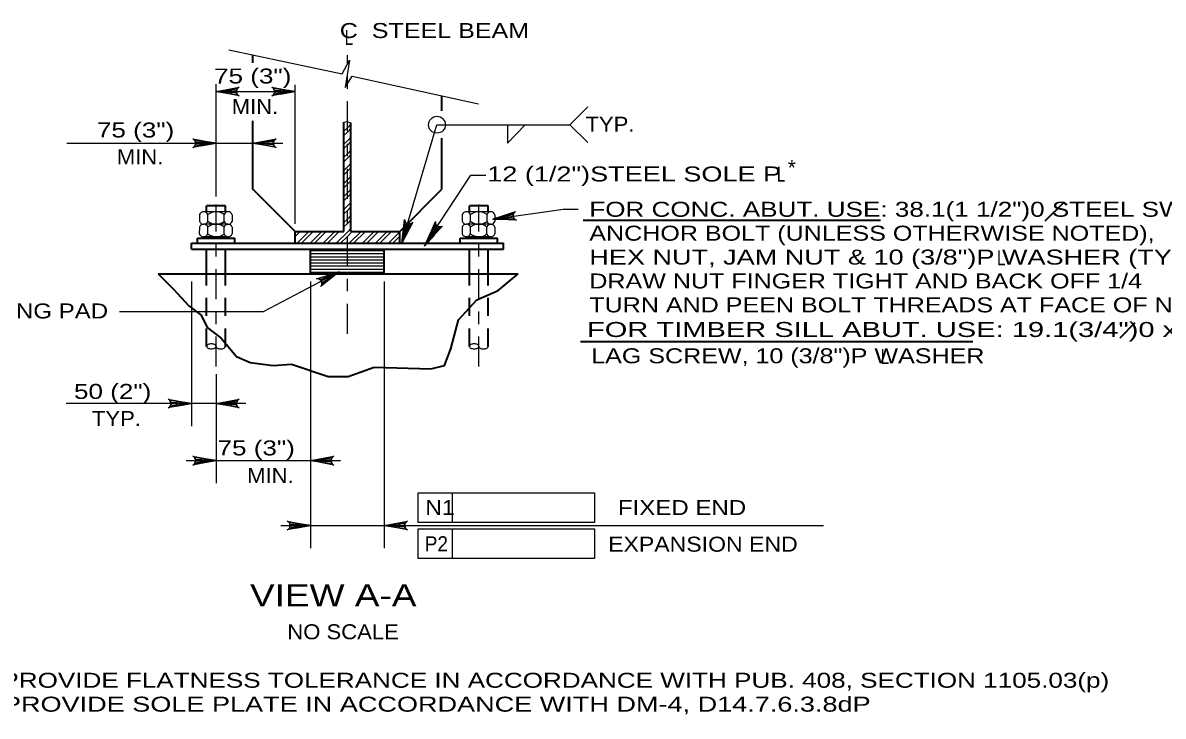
# Model space of a CAD drawing. Extents: x -11 to 79, y -154 to 0.
# Drawn here: x 14 to 23.13, y -147.7 to -142.15 of the extents above; entities that cross this region are included whole.
import ezdxf
from ezdxf.enums import TextEntityAlignment as Align

# ---------------------------------------------------------------- set-up
doc = ezdxf.new("R2010")
doc.units = 0
doc.header["$LTSCALE"] = 0.048
doc.linetypes.add('DOT_DASHED', pattern=[7.7, 5, -1.2, 0.3, -1.2])
doc.linetypes.add('MEDIUM_DASHED', pattern=[4.5, 3, -1.5])
for name, color, linetype, lineweight in [('3', 7, 'Continuous', 25), ('4', 7, 'Continuous', 25), ('8', 7, 'Continuous', 35)]:
    doc.layers.add(name, color=color, linetype=linetype, lineweight=lineweight)

msp = doc.modelspace()

# ---------------------------------------------------------------- hatches: boundary and pattern name
at = {"layer": '4'}
for points in [[(15.6685, -142.68467), (15.6685, -142.72458), (15.5485, -142.70458)], [(16.0615, -142.68467), (16.0615, -142.72458), (16.1815, -142.70458)], [(15.4285, -143.09783), (15.4285, -143.13783), (15.5485, -143.11783)], [(15.96383, -143.09783), (15.96383, -143.13783), (15.84383, -143.11783)], [(17.887, -143.72833), (17.8815, -143.68875), (17.76542, -143.72525)], [(17.09008, -143.80825), (17.052, -143.79592), (17.03408, -143.91625)], [(17.26717, -143.82925), (17.30067, -143.85108), (17.21833, -143.94067)], [(15.23167, -145.18158), (15.23167, -145.22158), (15.35167, -145.20158)], [(15.6685, -145.18158), (15.6685, -145.22158), (15.5485, -145.20158)], [(15.4285, -145.63775), (15.4285, -145.67775), (15.5485, -145.65775)], [(16.425, -145.63775), (16.425, -145.67775), (16.305, -145.65775)], [(16.185, -146.15725), (16.185, -146.19725), (16.305, -146.17725)], [(17.0155, -146.15725), (17.0155, -146.19725), (16.8955, -146.17725)]]:
    msp.add_hatch(color=256, dxfattribs=at).paths.add_polyline_path(points)

# ---------------------------------------------------------------- linework, layer by layer
at = {"layer": '3', "lineweight": 35}
for p, q in [((15.84383, -142.47458), (15.84383, -142.41092)), ((17.35675, -142.85967), (17.35675, -142.73908)), ((15.84383, -143.48667), (15.84383, -142.93842)), ((16.57217, -143.82442), (16.57217, -142.95008)), ((16.62842, -143.82442), (16.62842, -142.955)), ((17.35675, -143.48667), (17.35675, -143.0785)), ((15.6235, -143.61992), (15.4735, -143.61958)), ((15.4735, -143.66592), (15.4735, -143.61958)), ((15.6235, -143.66625), (15.6235, -143.61992)), ((17.577, -143.66592), (17.577, -143.61958)), ((17.727, -143.61992), (17.577, -143.61958)), ((17.727, -143.66625), (17.727, -143.61992)), ((16.1815, -143.91808), (16.1815, -143.82442)), ((16.1815, -143.82442), (16.57217, -143.82442)), ((16.62842, -143.82442), (17.019, -143.82442)), ((17.019, -143.91808), (17.019, -143.82442)), ((17.577, -143.87875), (17.577, -143.86592)), ((17.727, -143.87875), (17.727, -143.86625)), ((15.35167, -143.91808), (17.84883, -143.91808)), ((15.35167, -143.96533), (15.35167, -143.91808)), ((15.39892, -143.87875), (15.69817, -143.87875)), ((15.39892, -143.91808), (15.39892, -143.87875)), ((15.69817, -143.91808), (15.69817, -143.87875)), ((17.50242, -143.87875), (17.80158, -143.87875)), ((17.50242, -143.91808), (17.50242, -143.87875)), ((17.80158, -143.91808), (17.80158, -143.87875)), ((17.84883, -143.96533), (17.84883, -143.91808)), ((15.35167, -143.96533), (17.84883, -143.96533)), ((15.4735, -144.16225), (15.4735, -143.96533)), ((15.6235, -144.16225), (15.6235, -143.96533)), ((16.305, -144.16225), (16.305, -143.96533)), ((16.8955, -144.16225), (16.8955, -143.96533)), ((17.577, -144.16225), (17.577, -143.96533)), ((17.727, -144.16225), (17.727, -143.96533)), ((15.08642, -144.16225), (17.967, -144.16225))]:
    msp.add_line(p, q, dxfattribs=at)
at = {"layer": '3', "linetype": 'DOT_DASHED'}
for p, q in [((16.60025, -144.64183), (16.60025, -142.41183)), ((15.5485, -144.90458), (15.5485, -143.60717)), ((17.652, -144.90458), (17.652, -143.60717))]:
    msp.add_line(p, q, dxfattribs=at)
at = {"layer": '3'}
for p, q in [((16.57217, -142.95225), (16.57475, -142.94958)), ((16.57217, -143.43942), (16.60025, -143.41125)), ((16.60025, -143.41125), (16.62842, -143.38317)), ((16.57217, -143.47417), (16.60025, -143.44608)), ((16.60025, -143.44608), (16.62842, -143.41792)), ((16.60025, -143.51567), (16.62842, -143.48758)), ((16.57217, -143.54383), (16.60025, -143.51567)), ((16.57217, -143.57858), (16.60025, -143.5505)), ((16.60025, -143.5505), (16.62842, -143.52233)), ((16.60025, -143.62008), (16.62842, -143.59192)), ((15.64717, -143.66625), (15.448, -143.66583)), ((16.57217, -143.64817), (16.60025, -143.62008)), ((16.57217, -143.683), (16.60025, -143.65483)), ((16.60025, -143.65483), (16.62842, -143.62675)), ((17.75067, -143.66625), (17.5515, -143.66583)), ((15.41508, -143.689), (15.415, -143.74258)), ((15.647, -143.76625), (15.44775, -143.76583)), ((15.48292, -143.74275), (15.48308, -143.68908)), ((15.61417, -143.743), (15.61433, -143.68942)), ((15.67758, -143.6895), (15.6775, -143.74317)), ((16.57217, -143.75258), (16.60025, -143.7245)), ((16.57217, -143.78742), (16.60025, -143.75925)), ((16.60025, -143.7245), (16.62842, -143.69633)), ((16.60025, -143.75925), (16.62842, -143.73117)), ((17.51858, -143.689), (17.5185, -143.74258)), ((17.75042, -143.76625), (17.55125, -143.76583)), ((17.58642, -143.74275), (17.58658, -143.68908)), ((17.71767, -143.743), (17.71783, -143.68942)), ((17.78108, -143.6895), (17.781, -143.74317)), ((15.41492, -143.789), (15.41483, -143.84258)), ((15.64675, -143.86625), (15.44758, -143.86583)), ((15.4735, -143.87875), (15.4735, -143.86592)), ((15.48275, -143.84275), (15.48283, -143.78917)), ((15.614, -143.843), (15.61408, -143.78942)), ((15.6235, -143.87875), (15.6235, -143.86625)), ((15.67742, -143.78958), (15.67733, -143.84317)), ((16.1815, -143.83), (16.18717, -143.82442)), ((16.1815, -143.86483), (16.222, -143.82442)), ((16.19783, -143.91808), (16.29158, -143.82442)), ((16.23258, -143.91808), (16.32633, -143.82442)), ((16.30225, -143.91808), (16.39592, -143.82442)), ((16.337, -143.91808), (16.43075, -143.82442)), ((16.40658, -143.91808), (16.50033, -143.82442)), ((16.44142, -143.91808), (16.53517, -143.82442)), ((16.61542, -143.91808), (16.70917, -143.82442)), ((16.65017, -143.91808), (16.74392, -143.82442)), ((16.71983, -143.91808), (16.8135, -143.82442)), ((16.75458, -143.91808), (16.84833, -143.82442)), ((16.82417, -143.91808), (16.91792, -143.82442)), ((16.859, -143.91808), (16.95275, -143.82442)), ((16.92858, -143.91808), (17.019, -143.82775)), ((16.96342, -143.91808), (17.019, -143.8625)), ((17.51842, -143.789), (17.51825, -143.84258)), ((17.75025, -143.86625), (17.55108, -143.86583)), ((17.58625, -143.84275), (17.58633, -143.78917)), ((17.7175, -143.843), (17.71758, -143.78942)), ((17.78092, -143.78958), (17.78075, -143.84317)), ((16.305, -143.96542), (16.30492, -143.96533)), ((15.62483, -144.16225), (15.6235, -144.16092)), ((17.5695, -144.16225), (17.577, -144.15467))]:
    msp.add_line(p, q, dxfattribs=at)
at = {"layer": '3', "linetype": 'MEDIUM_DASHED', "lineweight": 35}
for p, q in [((15.4735, -144.74417), (15.4735, -144.16225)), ((15.6235, -144.74417), (15.6235, -144.16225)), ((17.577, -144.74417), (17.577, -144.16225)), ((17.727, -144.74417), (17.727, -144.16225))]:
    msp.add_line(p, q, dxfattribs=at)
at = {"layer": '3'}
for points in [[(16.57217, -142.95008), (16.598, -142.94525), (16.62842, -142.955)], [(16.57217, -143.02183), (16.60025, -142.99367), (16.62842, -142.96558)], [(16.57217, -143.05658), (16.60025, -143.0285), (16.62842, -143.00042)], [(16.57217, -143.12625), (16.60025, -143.09808), (16.62842, -143.07)], [(16.57217, -143.161), (16.60025, -143.13292), (16.62842, -143.10475)], [(16.57217, -143.23058), (16.60025, -143.2025), (16.62842, -143.17433)], [(16.57217, -143.26542), (16.60025, -143.23725), (16.62842, -143.20917)], [(16.57217, -143.335), (16.60025, -143.30692), (16.62842, -143.27875)], [(16.57217, -143.36983), (16.60025, -143.34167), (16.62842, -143.31358)], [(16.511, -143.91808), (16.60025, -143.82883), (16.62842, -143.80075)], [(16.54583, -143.91808), (16.60025, -143.86367), (16.63958, -143.82442)], [(16.305, -143.97667), (16.60025, -143.97667), (16.8955, -143.97667)], [(16.305, -144.00133), (16.60025, -144.00133), (16.8955, -144.00133)], [(16.305, -144.02592), (16.60025, -144.02592), (16.8955, -144.02592)], [(16.305, -144.0505), (16.60025, -144.0505), (16.8955, -144.0505)], [(16.305, -144.07517), (16.60025, -144.07517), (16.8955, -144.07517)], [(16.305, -144.09975), (16.60025, -144.09975), (16.8955, -144.09975)], [(16.305, -144.12433), (16.60025, -144.12433), (16.8955, -144.12433)], [(16.305, -144.14892), (16.60025, -144.14892), (16.8955, -144.14892)]]:
    msp.add_lwpolyline(points, dxfattribs=at)
at = {"layer": '3', "lineweight": 35}
msp.add_lwpolyline([(15.08642, -144.16225), (15.209, -144.28475), (15.33158, -144.4195), (15.42967, -144.49308), (15.47867, -144.59108), (15.589, -144.67683), (15.71158, -144.82383), (15.82192, -144.87292), (16.00575, -144.89742), (16.15283, -144.88517), (16.44708, -144.98317), (16.60642, -144.98317), (16.81475, -144.90967), (17.26833, -144.92192), (17.37867, -144.89742), (17.42767, -144.76258), (17.48892, -144.52983), (17.636, -144.3705), (17.80767, -144.297), (17.967, -144.16225)], dxfattribs=at)
at = {"layer": '3'}
for centre, radius, start, end in [((15.44903, -143.70227), 0.03646, 88.05447, 158.59459), ((15.44903, -143.70227), 0.03646, 21.16848, 88.05447), ((15.54849, -143.77042), 0.10439, 50.93154, 128.83154), ((15.64591, -143.69939), 0.03318, 17.33335, 162.42973), ((17.55252, -143.70227), 0.03646, 88.05447, 158.59459), ((17.55252, -143.70227), 0.03646, 21.16848, 88.05447), ((17.65198, -143.77042), 0.10439, 50.93154, 128.83154), ((17.7494, -143.69939), 0.03318, 17.33335, 162.42973), ((15.44883, -143.80228), 0.03646, 88.05447, 158.59459), ((15.44898, -143.7294), 0.03646, 201.16848, 271.7086), ((15.44898, -143.7294), 0.03646, 271.7086, 338.59459), ((15.44883, -143.80228), 0.03646, 21.16848, 88.05447), ((15.54829, -143.87044), 0.10439, 50.93154, 128.83154), ((15.54872, -143.66166), 0.10439, 230.93154, 308.83154), ((15.64571, -143.7994), 0.03318, 17.33335, 162.42973), ((15.64584, -143.73309), 0.03318, 197.33335, 342.42973), ((17.55231, -143.80228), 0.03646, 88.05447, 158.59459), ((17.55246, -143.7294), 0.03646, 201.16848, 271.7086), ((17.55246, -143.7294), 0.03646, 271.7086, 338.59459), ((17.55231, -143.80228), 0.03646, 21.16848, 88.05447), ((17.65177, -143.87044), 0.10439, 50.93154, 128.83154), ((17.6522, -143.66166), 0.10439, 230.93154, 308.83154), ((17.74919, -143.7994), 0.03318, 17.33335, 162.42973), ((17.74933, -143.73309), 0.03318, 197.33335, 342.42973), ((15.44877, -143.8294), 0.03646, 201.16848, 271.7086), ((15.44877, -143.8294), 0.03646, 271.7086, 338.59459), ((15.54851, -143.76166), 0.10439, 230.93154, 308.83154), ((15.64564, -143.83309), 0.03318, 197.33335, 342.42973), ((17.55226, -143.8294), 0.03646, 201.16848, 271.7086), ((17.55226, -143.8294), 0.03646, 271.7086, 338.59459), ((17.65199, -143.76166), 0.10439, 230.93154, 308.83154), ((17.74912, -143.83309), 0.03318, 197.33335, 342.42973), ((15.48477, -144.74317), 0.01111, 142.06928, 180.00001), ((15.48477, -144.74317), 0.01111, 180.00001, 217.93074), ((15.49728, -144.75292), 0.02696, 117.99032, 142.06928), ((15.49728, -144.73343), 0.02696, 217.93074, 242.0097), ((15.5056, -144.76858), 0.04469, 102.4157, 117.99032), ((15.5056, -144.71777), 0.04469, 242.0097, 257.58432), ((15.51108, -144.79346), 0.07017, 90.00001, 102.4157), ((15.51108, -144.69288), 0.07017, 257.58432, 270.00001), ((15.51108, -144.79346), 0.07017, 77.58432, 90.00001), ((15.51108, -144.69288), 0.07017, 270.00001, 282.4157), ((15.51656, -144.76858), 0.04469, 62.0097, 77.58432), ((15.51656, -144.71777), 0.04469, 282.4157, 297.99032), ((15.52488, -144.75292), 0.02696, 37.93074, 62.0097), ((15.52488, -144.73343), 0.02696, 297.99032, 322.06928), ((15.53739, -144.74317), 0.01111, 0.00001, 37.93074), ((15.53739, -144.74317), 0.01111, 322.06928, 0.00001), ((15.5596, -144.74395), 0.01111, 179.99999, 217.93072), ((15.5721, -144.73421), 0.02696, 217.93072, 242.00968), ((15.58043, -144.71855), 0.04469, 242.00968, 257.5843), ((15.5859, -144.69366), 0.07017, 257.5843, 269.99999), ((15.5859, -144.69366), 0.07017, 269.99999, 282.41568), ((15.59138, -144.71855), 0.04469, 282.41568, 297.9903), ((15.59971, -144.73421), 0.02696, 297.9903, 322.06926), ((15.61221, -144.74395), 0.01111, 322.06926, 359.99999), ((15.61221, -144.74395), 0.01111, 359.99999, 1.75704), ((17.58826, -144.74317), 0.01111, 142.06928, 180.00001), ((17.58826, -144.74317), 0.01111, 180.00001, 217.93074), ((17.60076, -144.75292), 0.02696, 117.99032, 142.06928), ((17.60076, -144.73343), 0.02696, 217.93074, 242.0097), ((17.60909, -144.76858), 0.04469, 102.4157, 117.99032), ((17.60909, -144.71777), 0.04469, 242.0097, 257.58432), ((17.61456, -144.79346), 0.07017, 90.00001, 102.4157), ((17.61456, -144.69288), 0.07017, 257.58432, 270.00001), ((17.61456, -144.79346), 0.07017, 77.58432, 90.00001), ((17.61456, -144.69288), 0.07017, 270.00001, 282.4157), ((17.62004, -144.76858), 0.04469, 62.0097, 77.58432), ((17.62004, -144.71777), 0.04469, 282.4157, 297.99032), ((17.62837, -144.75292), 0.02696, 37.93074, 62.0097), ((17.62837, -144.73343), 0.02696, 297.99032, 322.06928), ((17.64087, -144.74317), 0.01111, 0.00001, 37.93074), ((17.64087, -144.74317), 0.01111, 322.06928, 0.00001), ((17.66308, -144.74395), 0.01111, 179.99999, 217.93072), ((17.67559, -144.73421), 0.02696, 217.93072, 242.00968), ((17.68391, -144.71855), 0.04469, 242.00968, 257.5843), ((17.68939, -144.69366), 0.07017, 257.5843, 269.99999), ((17.68939, -144.69366), 0.07017, 269.99999, 282.41568), ((17.69487, -144.71855), 0.04469, 282.41568, 297.9903), ((17.70319, -144.73421), 0.02696, 297.9903, 322.06926), ((17.71569, -144.74395), 0.01111, 322.06926, 359.99999), ((17.71569, -144.74395), 0.01111, 359.99999, 1.75704)]:
    msp.add_arc(centre, radius, start, end, dxfattribs=at)
at = {"layer": '4'}
for p, q in [((15.65025, -142.36975), (16.55775, -142.56308)), ((16.55775, -142.56308), (16.61758, -142.45283)), ((16.61758, -142.45283), (16.58292, -142.67133)), ((16.58292, -142.67133), (16.63767, -142.58033)), ((16.63767, -142.58033), (17.65, -142.80375)), ((15.5485, -143.54467), (15.5485, -142.64633)), ((16.1815, -143.76192), (16.1815, -142.65142)), ((15.5485, -142.70458), (16.1815, -142.70458)), ((18.37992, -142.96983), (18.52467, -142.82675)), ((17.03675, -143.91808), (17.31717, -142.96983)), ((17.31717, -142.96983), (18.37992, -142.96983)), ((17.88125, -143.11658), (18.02267, -142.96983)), ((17.88125, -142.96983), (17.88125, -143.11658)), ((18.37992, -142.96983), (18.52467, -143.11292)), ((14.3555, -143.11783), (16.08383, -143.11783)), ((17.23125, -143.91808), (17.58833, -143.37358)), ((17.58833, -143.37358), (17.70833, -143.37358)), ((17.76492, -143.72525), (18.32683, -143.64642)), ((18.32683, -143.64642), (18.44683, -143.64642)), ((15.35167, -144.22475), (15.35167, -145.38158)), ((16.535, -144.14617), (15.92683, -144.46617)), ((16.305, -144.22475), (16.305, -146.35717)), ((16.8955, -144.22475), (16.8955, -146.35717)), ((15.92683, -144.46617), (14.77658, -144.46617)), ((15.5485, -144.96708), (15.5485, -145.83775)), ((15.78725, -145.20158), (14.34942, -145.20158)), ((15.30975, -145.65775), (16.545, -145.65775)), ((17.16575, -145.91658), (18.57783, -145.91658)), ((17.16575, -146.15275), (17.16575, -145.91658)), ((17.44142, -146.15275), (17.44142, -145.91658)), ((18.57783, -145.91658), (18.57783, -146.15275)), ((16.06625, -146.17725), (20.41, -146.17725)), ((18.57783, -146.15275), (17.16575, -146.15275)), ((17.16575, -146.20392), (18.57783, -146.20392)), ((17.16575, -146.44017), (17.16575, -146.20392)), ((17.44142, -146.44017), (17.44142, -146.20392)), ((18.57783, -146.20392), (18.57783, -146.44017)), ((18.57783, -146.44017), (17.16575, -146.44017))]:
    msp.add_line(p, q, dxfattribs=at)
at = {"layer": '4', "lineweight": 35}
for p, q in [((22.18667, -143.73975), (22.34033, -143.586)), ((18.48733, -143.7325), (20.86658, -143.7325)), ((22.78525, -144.6745), (22.90725, -144.5525)), ((18.46592, -144.70467), (21.60792, -144.70467))]:
    msp.add_line(p, q, dxfattribs=at)
at = {"layer": '4'}
for points in [[(15.5485, -142.70458), (15.73492, -142.66967), (15.72058, -142.67958), (15.71317, -142.69208), (15.711, -142.70458), (15.71317, -142.71708), (15.72058, -142.72958), (15.73492, -142.7395), (15.5485, -142.70458), (15.72058, -142.72958), (15.71317, -142.71708), (15.5485, -142.70458), (15.711, -142.70458), (15.71317, -142.69208), (15.5485, -142.70458), (15.72058, -142.67958)], [(16.1815, -142.70458), (15.99508, -142.7395), (16.00942, -142.72958), (16.01683, -142.71708), (16.019, -142.70458), (16.01683, -142.69208), (16.00942, -142.67958), (15.99508, -142.66967), (16.1815, -142.70458), (16.00942, -142.67958), (16.01683, -142.69208), (16.1815, -142.70458), (16.019, -142.70458), (16.01683, -142.71708), (16.1815, -142.70458), (16.00942, -142.72958)], [(15.5485, -143.11783), (15.36208, -143.15275), (15.37642, -143.14283), (15.38383, -143.13033), (15.386, -143.11783), (15.38383, -143.10533), (15.37642, -143.09283), (15.36208, -143.08292), (15.5485, -143.11783), (15.37642, -143.09283), (15.38383, -143.10533), (15.5485, -143.11783), (15.386, -143.11783), (15.38383, -143.13033), (15.5485, -143.11783), (15.37642, -143.14283)], [(15.84383, -143.11783), (16.03025, -143.08292), (16.01592, -143.09283), (16.0085, -143.10533), (16.00633, -143.11783), (16.0085, -143.13033), (16.01592, -143.14283), (16.03025, -143.15275), (15.84383, -143.11783), (16.01592, -143.14283), (16.0085, -143.13033), (15.84383, -143.11783), (16.00633, -143.11783), (16.0085, -143.10533), (15.84383, -143.11783), (16.01592, -143.09283)], [(17.76492, -143.72525), (17.94467, -143.66475), (17.93183, -143.67658), (17.92625, -143.69), (17.92583, -143.70267), (17.92967, -143.71475), (17.93875, -143.72608), (17.95442, -143.734), (17.76492, -143.72525), (17.93875, -143.72608), (17.92967, -143.71475), (17.76492, -143.72525), (17.92583, -143.70267), (17.92625, -143.69), (17.76492, -143.72525), (17.93183, -143.67658)], [(17.03675, -143.91808), (17.05608, -143.72942), (17.06158, -143.746), (17.07142, -143.75667), (17.08283, -143.76225), (17.09542, -143.76375), (17.1095, -143.76017), (17.12317, -143.74925), (17.03675, -143.91808), (17.1095, -143.76017), (17.09542, -143.76375), (17.03675, -143.91808), (17.08283, -143.76225), (17.07142, -143.75667), (17.03675, -143.91808), (17.06158, -143.746)], [(17.23125, -143.91808), (17.30425, -143.743), (17.30467, -143.7605), (17.31108, -143.77358), (17.32033, -143.78217), (17.332, -143.78725), (17.3465, -143.78792), (17.36267, -143.78133), (17.23125, -143.91808), (17.3465, -143.78792), (17.332, -143.78725), (17.23125, -143.91808), (17.32033, -143.78217), (17.31108, -143.77358), (17.23125, -143.91808), (17.30467, -143.7605)], [(16.535, -144.14625), (16.38633, -144.26392), (16.39442, -144.24842), (16.39508, -144.23392), (16.39117, -144.22192), (16.3835, -144.21183), (16.37108, -144.20417), (16.35375, -144.20208), (16.535, -144.14625), (16.37108, -144.20417), (16.3835, -144.21183), (16.535, -144.14625), (16.39117, -144.22192), (16.39508, -144.23392), (16.535, -144.14625), (16.39442, -144.24842)], [(15.35167, -145.20158), (15.16525, -145.2365), (15.17958, -145.22658), (15.187, -145.21408), (15.18917, -145.20158), (15.187, -145.18908), (15.17958, -145.17658), (15.16525, -145.16667), (15.35167, -145.20158), (15.17958, -145.17658), (15.187, -145.18908), (15.35167, -145.20158), (15.18917, -145.20158), (15.187, -145.21408), (15.35167, -145.20158), (15.17958, -145.22658)], [(15.5485, -145.20158), (15.73492, -145.16667), (15.72058, -145.17658), (15.71317, -145.18908), (15.711, -145.20158), (15.71317, -145.21408), (15.72058, -145.22658), (15.73492, -145.2365), (15.5485, -145.20158), (15.72058, -145.22658), (15.71317, -145.21408), (15.5485, -145.20158), (15.711, -145.20158), (15.71317, -145.18908), (15.5485, -145.20158), (15.72058, -145.17658)], [(15.5485, -145.65775), (15.36208, -145.69267), (15.37642, -145.68275), (15.38383, -145.67025), (15.386, -145.65775), (15.38383, -145.64525), (15.37642, -145.63275), (15.36208, -145.62283), (15.5485, -145.65775), (15.37642, -145.63275), (15.38383, -145.64525), (15.5485, -145.65775), (15.386, -145.65775), (15.38383, -145.67025), (15.5485, -145.65775), (15.37642, -145.68275)], [(16.305, -145.65775), (16.49142, -145.62283), (16.47708, -145.63275), (16.46967, -145.64525), (16.4675, -145.65775), (16.46967, -145.67025), (16.47708, -145.68275), (16.49142, -145.69267), (16.305, -145.65775), (16.47708, -145.68275), (16.46967, -145.67025), (16.305, -145.65775), (16.4675, -145.65775), (16.46967, -145.64525), (16.305, -145.65775), (16.47708, -145.63275)], [(16.305, -146.17725), (16.11858, -146.21217), (16.13292, -146.20225), (16.14033, -146.18975), (16.1425, -146.17725), (16.14033, -146.16475), (16.13292, -146.15225), (16.11858, -146.14233), (16.305, -146.17725), (16.13292, -146.15225), (16.14033, -146.16475), (16.305, -146.17725), (16.1425, -146.17725), (16.14033, -146.18975), (16.305, -146.17725), (16.13292, -146.20225)], [(16.8955, -146.17725), (17.08192, -146.14233), (17.06758, -146.15225), (17.06017, -146.16475), (17.058, -146.17725), (17.06017, -146.18975), (17.06758, -146.20225), (17.08192, -146.21217), (16.8955, -146.17725), (17.06758, -146.20225), (17.06017, -146.18975), (16.8955, -146.17725), (17.058, -146.17725), (17.06017, -146.16475), (16.8955, -146.17725), (17.06758, -146.15225)]]:
    msp.add_lwpolyline(points, dxfattribs=at)
for points in [[(15.6685, -142.68467), (15.6685, -142.72458), (15.5485, -142.70458)], [(16.0615, -142.68467), (16.0615, -142.72458), (16.1815, -142.70458)], [(15.4285, -143.09783), (15.4285, -143.13783), (15.5485, -143.11783)], [(15.96383, -143.09783), (15.96383, -143.13783), (15.84383, -143.11783)], [(17.887, -143.72833), (17.8815, -143.68875), (17.76542, -143.72525)], [(17.09008, -143.80825), (17.052, -143.79592), (17.03408, -143.91625)], [(17.26717, -143.82925), (17.30067, -143.85108), (17.21833, -143.94067)], [(15.23167, -145.18158), (15.23167, -145.22158), (15.35167, -145.20158)], [(15.6685, -145.18158), (15.6685, -145.22158), (15.5485, -145.20158)], [(15.4285, -145.63775), (15.4285, -145.67775), (15.5485, -145.65775)], [(16.425, -145.63775), (16.425, -145.67775), (16.305, -145.65775)], [(16.185, -146.15725), (16.185, -146.19725), (16.305, -146.17725)], [(17.0155, -146.15725), (17.0155, -146.19725), (16.8955, -146.17725)]]:
    msp.add_lwpolyline(points, close=True, dxfattribs=at)
msp.add_circle((17.31717, -142.96983), 0.06746, dxfattribs=at)
for centre in [(15.5596, -144.74317), (17.66308, -144.74317)]:
    msp.add_arc(centre, 0.01111, 180.00001, 182.00778, dxfattribs=at)
at = {"layer": '8'}
for p, q in [((16.1815, -143.82442), (15.84383, -143.48667)), ((17.019, -143.82442), (17.35675, -143.48667))]:
    msp.add_line(p, q, dxfattribs=at)

# ---------------------------------------------------------------- texts
at = {"layer": '4'}
for s, width, p in [('C  STEEL BEAM', 1.25, (16.53892, -142.27608)), ('L', 0.75, (16.57825, -142.3325)), ('75 (3")', 1.3, (15.53275, -142.64008)), ('MIN.', 1.1, (15.67408, -142.88442)), ('75 (3")', 1.3, (14.595, -143.07192)), ('TYP.', 1.1, (18.50583, -143.02583)), ('MIN.', 1.1, (14.75417, -143.2875)), ('12 (1/2")STEEL SOLE P', 1.35, (17.7195, -143.424)), ('*', 1.05, (20.125, -143.37292)), ('FOR CONC. ABUT. USE: 38.1(1 1/2")0 STEEL SWEDGE', 1.3, (18.53683, -143.70642)), ('ANCHOR BOLT (UNLESS OTHERWISE NOTED), ', 1.25, (18.53683, -143.89767)), ('HEX NUT, JAM NUT & 10 (3/8")P WASHER (TYP.)', 1.35, (18.53683, -144.08883)), ('L', 0.75, (21.80125, -144.0955)), ('DRAW NUT FINGER TIGHT AND BACK OFF 1/4', 1.25, (18.53683, -144.28008)), ('TURN AND PEEN BOLT THREADS AT FACE OF NUTS.', 1.25, (18.53683, -144.47133)), ('FOR TIMBER SILL ABUT. USE: 19.1(3/4")0 x 305 (1\'-0") LONG ', 1.45, (18.518, -144.66833)), ('LAG SCREW, 10 (3/8")P WASHER', 1.25, (18.55183, -144.87875)), ('L', 0.75, (20.8705, -144.88375)), ('TYP.', 1.1, (14.555, -145.38025)), ('75 (3")', 1.3, (15.5605, -145.61583)), ('MIN.', 1.1, (15.79758, -145.8375)), ('NO SCALE', 1.1, (16.11917, -147.08717)), ('(a) PROVIDE FLATNESS TOLERANCE IN ACCORDANCE WITH PUB. 408, SECTION 1105.03(p)', 1.3, (13.51767, -147.47525)), ('(b) PROVIDE SOLE PLATE IN ACCORDANCE WITH DM-4, D14.7.6.3.8dP', 1.35, (13.51767, -147.6665))]:
    msp.add_text(s, height=0.12, dxfattribs=dict(at, width=width)).set_placement(p)
for s, width, p in [('L', 0.75, (20.10508, -143.42508)), ('ELASTOMERIC BEARING PAD', 1.2, (14.68492, -144.52008))]:
    msp.add_text(s, height=0.12, dxfattribs=dict(at, width=width)).set_placement(p, align=Align.RIGHT)
for s, height, width, p in [('50 (2")', 0.12, 1.3, (14.72087, -145.16392)), ('N1', 0.12, 1.15, (17.34196, -146.09275)), ('FIXED END', 0.12, 1.2, (19.27887, -146.09333)), ('P2', 0.12, 0.95, (17.31229, -146.38292)), ('EXPANSION END', 0.12, 1.15, (19.44625, -146.38633)), ('VIEW A-A', 0.1772, 1.25, (16.48687, -146.82342))]:
    msp.add_text(s, height=height, dxfattribs=dict(at, width=width)).set_placement(p, align=Align.CENTER)

doc.saveas('drawing.dxf')
